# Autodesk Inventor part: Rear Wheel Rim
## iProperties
Shininess: 72.0
Angle Display Precision: 2
Document Length Units: 11269
Document Angle Units: 11279
Document Time Units: 11290
Document Mass Units: 11283
Document Length Units Precision: 3
Document Angle Units Precision: 2
Compacted: True
Created: 2001-08
Part Number: Rear Wheel Rim
Document SubType Name: Modeling
Designer: Martin Budgell
Density: 0.0
Volumn: 0.0
Area: 0.0
PropertySet Name: Model Information
Control State: 0
Master: False
Checked Out: False
Author: Martin Budgell
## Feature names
1. Revolution1
2. Fillet1
3. Extrusion1
4. Extrusion2
5. Revolution2
6. Extrusion5
7. Hole2
8. Fillet3
9. Fillet4
10. Extrusion4
11. Fillet6
12. Fillet7
13. Extrusion6
14. Circular Pattern1
15. Chamfer2
16. Fillet8
17. Fillet9
18. Revolution3
19. Fillet10
20. Extrusion7
21. Extrusion8
22. Fillet11
23. Fillet12
